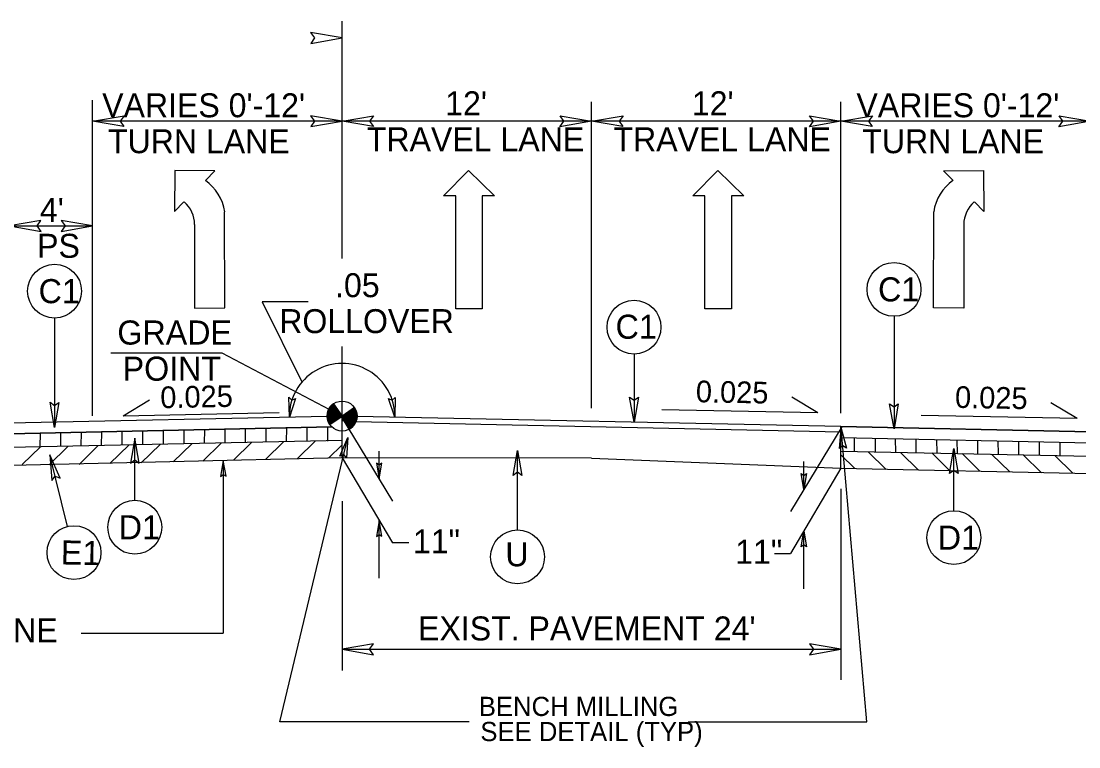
# Model space of a CAD drawing. Extents: x 2176024 to 2177225, y 75947 to 76635.
# Drawn here: x 2176290.4 to 2176341.3, y 76551.8 to 76586.8 of the extents above; entities that cross this region are included whole.
import ezdxf

# ---------------------------------------------------------------- set-up
doc = ezdxf.new("R2010")
doc.units = 0
for name, color, linetype in [('Exist XS Ground Line', 7, 'Continuous'), ('Old_Level_1', 7, 'Continuous'), ('Old_Level_11', 7, 'Continuous'), ('Old_Level_4', 7, 'Continuous'), ('Prop Dimension', 7, 'Continuous'), ('Prop Lane Arrow CELL', 7, 'Continuous'), ('Typical Curb CELL', 7, 'Continuous'), ('Typical Grade Point Symbol CELL', 7, 'Continuous'), ('Typical Pavement Slope CELL', 7, 'Continuous'), ('Typical Pavement Slope Information CELL', 7, 'Continuous'), ('Typical Shoulder Slope CELL', 7, 'Continuous'), ('Typical Slope Point Local CELL', 7, 'Continuous'), ('Typical Terminator CELL', 7, 'Continuous'), ('Typical Text General CELL', 7, 'Continuous')]:
    doc.layers.add(name, color=color, linetype=linetype)

msp = doc.modelspace()

# ---------------------------------------------------------------- linework, layer by layer
at = {"layer": 'Exist XS Ground Line'}
for q in [(2176305.841, 76565.736), (2176329.841, 76565.236)]:
    msp.add_line((2176317.841, 76565.72), q, dxfattribs=at)
at = {"layer": 'Old_Level_1'}
for p, q in [((2176291.326, 76566.266), (2176291.331, 76566.935)), ((2176292.315, 76566.283), (2176292.32, 76566.956)), ((2176293.298, 76566.302), (2176293.303, 76566.976)), ((2176294.275, 76566.325), (2176294.281, 76566.997)), ((2176295.264, 76566.347), (2176295.27, 76567.017)), ((2176296.253, 76566.366), (2176296.259, 76567.038)), ((2176297.25, 76566.389), (2176297.256, 76567.059)), ((2176298.24, 76566.412), (2176298.245, 76567.079)), ((2176299.229, 76566.433), (2176299.234, 76567.1)), ((2176300.21, 76566.454), (2176300.215, 76567.12)), ((2176301.189, 76566.472), (2176301.195, 76567.141)), ((2176302.186, 76566.493), (2176302.192, 76567.161)), ((2176303.174, 76566.515), (2176303.179, 76567.182)), ((2176304.163, 76566.529), (2176304.169, 76567.203)), ((2176305.153, 76566.549), (2176305.158, 76567.223)), ((2176296.184, 76565.5), (2176297.084, 76566.383)), ((2176297.722, 76565.551), (2176298.607, 76566.422)), ((2176299.15, 76565.586), (2176300.023, 76566.444)), ((2176300.618, 76565.623), (2176301.485, 76566.476)), ((2176302.155, 76565.654), (2176303.024, 76566.509)), ((2176303.679, 76565.694), (2176304.54, 76566.541)), ((2176330.496, 76566.049), (2176330.491, 76566.698)), ((2176331.502, 76566.024), (2176331.497, 76566.677)), ((2176332.476, 76566.012), (2176332.471, 76566.657)), ((2176333.466, 76565.983), (2176333.46, 76566.637)), ((2176334.463, 76565.976), (2176334.457, 76566.616)), ((2176335.442, 76565.955), (2176335.437, 76566.595)), ((2176336.423, 76565.935), (2176336.418, 76566.575)), ((2176337.412, 76565.91), (2176337.407, 76566.554)), ((2176338.401, 76565.891), (2176338.396, 76566.534)), ((2176339.399, 76565.867), (2176339.393, 76566.513)), ((2176340.388, 76565.854), (2176340.382, 76566.492)), ((2176290.46, 76565.413), (2176291.331, 76566.269)), ((2176291.749, 76565.403), (2176292.654, 76566.293)), ((2176293.197, 76565.425), (2176294.115, 76566.328)), ((2176294.664, 76565.462), (2176295.576, 76566.358)), ((2176305.188, 76565.727), (2176305.841, 76566.369)), ((2176330.512, 76565.222), (2176329.843, 76565.88)), ((2176332.022, 76565.185), (2176331.155, 76566.037)), ((2176333.57, 76565.146), (2176332.702, 76566.001)), ((2176335.069, 76565.131), (2176334.205, 76565.981)), ((2176336.527, 76565.104), (2176335.669, 76565.947)), ((2176337.957, 76565.067), (2176337.091, 76565.919)), ((2176339.493, 76565.017), (2176338.61, 76565.884)), ((2176340.992, 76565.001), (2176340.125, 76565.853))]:
    msp.add_line(p, q, dxfattribs=at)
at = {"layer": 'Old_Level_11'}
for p, q in [((2176304.207, 76573.248), (2176301.999, 76573.248)), ((2176301.999, 76573.248), (2176303.911, 76569.392)), ((2176332.395, 76572.555), (2176332.395, 76567.14)), ((2176292.006, 76572.47), (2176292.006, 76567.208)), ((2176294.722, 76570.79), (2176300.053, 76570.79)), ((2176300.053, 76570.79), (2176305.841, 76567.75)), ((2176319.887, 76570.735), (2176319.887, 76567.457)), ((2176295.871, 76563.695), (2176295.871, 76566.691)), ((2176292.635, 76562.435), (2176291.789, 76565.878)), ((2176314.282, 76562.267), (2176314.282, 76566.097)), ((2176335.273, 76563.195), (2176335.273, 76566.191))]:
    msp.add_line(p, q, dxfattribs=at)
for points in [[(2176292.213, 76568.408), (2176292.006, 76567.208), (2176291.793, 76568.414), (2176292.006, 76568.261)], [(2176320.094, 76568.657), (2176319.887, 76567.457), (2176319.674, 76568.664), (2176319.887, 76568.511)], [(2176332.601, 76568.34), (2176332.395, 76567.14), (2176332.181, 76568.347), (2176332.395, 76568.194)], [(2176329.774, 76566.188), (2176329.859, 76567.159), (2176330.109, 76566.211), (2176329.929, 76566.319)], [(2176296.078, 76565.491), (2176295.871, 76566.691), (2176295.658, 76565.485), (2176295.871, 76565.638)], [(2176305.736, 76565.825), (2176306.123, 76566.719), (2176306.062, 76565.741), (2176305.925, 76565.9)], [(2176292.279, 76564.763), (2176291.789, 76565.878), (2176291.874, 76564.656), (2176292.043, 76564.856)], [(2176314.076, 76564.897), (2176314.282, 76566.097), (2176314.496, 76564.89), (2176314.282, 76565.044)], [(2176335.066, 76564.991), (2176335.273, 76566.191), (2176335.486, 76564.985), (2176335.273, 76565.138)]]:
    msp.add_lwpolyline(points, close=True, dxfattribs=at)
for centre in [(2176292.012, 76573.766), (2176332.395, 76573.851), (2176319.887, 76572.031), (2176295.871, 76562.399), (2176335.273, 76561.899), (2176292.945, 76561.177), (2176314.282, 76560.971)]:
    msp.add_circle(centre, 1.296, dxfattribs=at)
msp.add_arc((2176305.841, 76567.75), 2.534, 358.8065, 181.1935, dxfattribs=at)
at = {"layer": 'Old_Level_4'}
for p, q in [((2176310.727, 76578.354), (2176311.929, 76579.576)), ((2176311.929, 76579.576), (2176313.171, 76578.354)), ((2176322.717, 76578.354), (2176323.92, 76579.576)), ((2176323.92, 76579.576), (2176325.162, 76578.354)), ((2176311.309, 76578.354), (2176310.727, 76578.354)), ((2176311.309, 76572.922), (2176311.309, 76578.354)), ((2176313.171, 76578.354), (2176312.589, 76578.354)), ((2176312.589, 76578.354), (2176312.589, 76572.922)), ((2176323.299, 76578.354), (2176322.717, 76578.354)), ((2176323.299, 76572.922), (2176323.299, 76578.354)), ((2176325.162, 76578.354), (2176324.58, 76578.354)), ((2176324.58, 76578.354), (2176324.58, 76572.922)), ((2176312.589, 76572.922), (2176311.309, 76572.922)), ((2176324.58, 76572.922), (2176323.299, 76572.922))]:
    msp.add_line(p, q, dxfattribs=at)
at = {"layer": 'Prop Dimension'}
for p, q in [((2176305.841, 76575.332), (2176305.841, 76586.766)), ((2176293.841, 76567.766), (2176293.841, 76582.965)), ((2176317.841, 76568.127), (2176317.841, 76582.883)), ((2176329.841, 76567.899), (2176329.841, 76582.883)), ((2176305.841, 76581.946), (2176293.841, 76581.946)), ((2176317.841, 76581.946), (2176305.841, 76581.946)), ((2176329.841, 76581.946), (2176317.841, 76581.946)), ((2176341.841, 76581.946), (2176329.841, 76581.946)), ((2176289.841, 76576.903), (2176293.841, 76576.903)), ((2176305.841, 76567.75), (2176305.841, 76571.093)), ((2176305.796, 76567.737), (2176308.266, 76563.655)), ((2176329.886, 76567.237), (2176327.416, 76563.155)), ((2176331.081, 76553.036), (2176329.859, 76567.159)), ((2176302.847, 76553.036), (2176306.123, 76566.719)), ((2176307.629, 76564.73), (2176307.629, 76566.058)), ((2176300.129, 76565.605), (2176300.129, 76557.301)), ((2176305.841, 76565.736), (2176308.266, 76561.641)), ((2176328.052, 76564.23), (2176328.052, 76565.558)), ((2176329.841, 76565.236), (2176327.416, 76561.141)), ((2176329.841, 76564.24), (2176329.841, 76555.057)), ((2176305.841, 76563.661), (2176305.841, 76555.497)), ((2176307.629, 76559.94), (2176307.629, 76562.716)), ((2176328.052, 76559.44), (2176328.052, 76562.216)), ((2176309.046, 76561.641), (2176308.266, 76561.641)), ((2176326.636, 76561.141), (2176327.416, 76561.141)), ((2176293.298, 76557.301), (2176300.129, 76557.301)), ((2176305.841, 76556.522), (2176329.841, 76556.522)), ((2176311.958, 76553.036), (2176302.847, 76553.036)), ((2176322.488, 76553.036), (2176331.081, 76553.036))]:
    msp.add_line(p, q, dxfattribs=at)
at = {"layer": 'Prop Lane Arrow CELL'}
for p, q in [((2176297.794, 76579.576), (2176297.775, 76577.601)), ((2176299.725, 76579.558), (2176297.794, 76579.576)), ((2176299.265, 76579.096), (2176299.725, 76579.558)), ((2176334.773, 76579.558), (2176336.703, 76579.576)), ((2176335.233, 76579.096), (2176334.773, 76579.558)), ((2176336.703, 76579.576), (2176336.722, 76577.601)), ((2176297.775, 76577.601), (2176298.235, 76578.063)), ((2176300.198, 76572.955), (2176300.189, 76577.584)), ((2176334.3, 76572.955), (2176334.308, 76577.584)), ((2176336.722, 76577.601), (2176336.262, 76578.063)), ((2176298.742, 76576.967), (2176298.749, 76572.952)), ((2176335.755, 76576.967), (2176335.748, 76572.952)), ((2176298.749, 76572.952), (2176300.198, 76572.955)), ((2176335.748, 76572.952), (2176334.3, 76572.955))]:
    msp.add_line(p, q, dxfattribs=at)
for centre, radius, start, end in [((2176297.919, 76577.232), 2.305, 8.7824, 54.0941), ((2176336.579, 76577.232), 2.305, 125.9059, 171.2176), ((2176297.312, 76576.969), 1.437, 0.1063, 49.7645), ((2176337.185, 76576.969), 1.437, 130.2355, 179.8937)]:
    msp.add_arc(centre, radius, start, end, dxfattribs=at)
at = {"layer": 'Typical Curb CELL'}
for p, q in [((2176305.841, 76565.736), (2176305.841, 76567.75)), ((2176329.841, 76565.236), (2176329.841, 76567.25))]:
    msp.add_line(p, q, dxfattribs=at)
at = {"layer": 'Typical Grade Point Symbol CELL'}
for p, q in [((2176305.429, 76568.342), (2176305.841, 76567.75)), ((2176305.841, 76567.75), (2176306.432, 76568.162)), ((2176305.248, 76567.34), (2176305.841, 76567.75)), ((2176305.841, 76567.75), (2176305.248, 76567.34)), ((2176306.253, 76567.158), (2176305.841, 76567.75))]:
    msp.add_line(p, q, dxfattribs=at)
for points in [[(2176305.596, 76568.102), (2176305.12, 76567.771)], [(2176305.604, 76568.091), (2176305.12, 76567.754)], [(2176305.612, 76568.079), (2176305.12, 76567.737)], [(2176305.587, 76568.114), (2176305.121, 76567.789)], [(2176305.62, 76568.067), (2176305.121, 76567.719)], [(2176305.629, 76568.055), (2176305.121, 76567.702)], [(2176305.579, 76568.126), (2176305.122, 76567.808)], [(2176305.637, 76568.043), (2176305.123, 76567.685)], [(2176305.571, 76568.138), (2176305.124, 76567.827)], [(2176305.645, 76568.031), (2176305.124, 76567.669)], [(2176305.563, 76568.15), (2176305.126, 76567.846)], [(2176305.653, 76568.02), (2176305.126, 76567.653)], [(2176305.554, 76568.162), (2176305.128, 76567.865)], [(2176305.661, 76568.008), (2176305.129, 76567.637)], [(2176305.546, 76568.173), (2176305.132, 76567.885)], [(2176305.67, 76567.996), (2176305.132, 76567.622)], [(2176305.678, 76567.984), (2176305.135, 76567.606)], [(2176305.538, 76568.185), (2176305.137, 76567.906)], [(2176305.686, 76567.972), (2176305.138, 76567.591)], [(2176305.694, 76567.96), (2176305.141, 76567.575)], [(2176305.53, 76568.197), (2176305.142, 76567.927)], [(2176305.703, 76567.949), (2176305.145, 76567.561)], [(2176305.521, 76568.209), (2176305.148, 76567.949)], [(2176305.711, 76567.937), (2176305.149, 76567.546)], [(2176305.513, 76568.221), (2176305.154, 76567.971)], [(2176305.719, 76567.925), (2176305.154, 76567.531)], [(2176305.727, 76567.913), (2176305.159, 76567.518)], [(2176305.505, 76568.233), (2176305.162, 76567.994)], [(2176305.497, 76568.244), (2176305.171, 76568.017)], [(2176305.489, 76568.256), (2176305.181, 76568.042)], [(2176305.48, 76568.268), (2176305.194, 76568.069)], [(2176305.472, 76568.28), (2176305.208, 76568.096)], [(2176305.464, 76568.292), (2176305.225, 76568.125)], [(2176305.456, 76568.304), (2176305.244, 76568.156)], [(2176305.447, 76568.315), (2176305.271, 76568.193)], [(2176305.439, 76568.327), (2176305.305, 76568.234)], [(2176305.431, 76568.339), (2176305.366, 76568.294)], [(2176306.436, 76568.156), (2176306.436, 76568.156), (2176305.844, 76567.745)], [(2176306.444, 76568.145), (2176305.853, 76567.733)], [(2176306.451, 76568.132), (2176305.861, 76567.721)], [(2176306.46, 76568.12), (2176305.869, 76567.709)], [(2176306.466, 76568.107), (2176305.877, 76567.697)], [(2176306.473, 76568.095), (2176305.886, 76567.686)], [(2176306.48, 76568.082), (2176305.894, 76567.674)], [(2176306.487, 76568.069), (2176305.902, 76567.662)], [(2176306.494, 76568.056), (2176305.91, 76567.65)], [(2176306.5, 76568.043), (2176305.919, 76567.638)], [(2176306.505, 76568.029), (2176305.927, 76567.626)], [(2176306.511, 76568.015), (2176305.935, 76567.615)], [(2176306.517, 76568.002), (2176305.943, 76567.603)], [(2176306.521, 76567.987), (2176305.952, 76567.591)], [(2176306.526, 76567.973), (2176305.96, 76567.579)], [(2176306.531, 76567.959), (2176305.968, 76567.567)], [(2176306.535, 76567.944), (2176305.976, 76567.555)], [(2176306.539, 76567.93), (2176305.984, 76567.544)], [(2176306.542, 76567.914), (2176305.993, 76567.532)], [(2176305.736, 76567.901), (2176305.164, 76567.503)], [(2176305.744, 76567.889), (2176305.169, 76567.49)], [(2176305.752, 76567.878), (2176305.175, 76567.476)], [(2176305.76, 76567.866), (2176305.18, 76567.462)], [(2176305.769, 76567.854), (2176305.186, 76567.449)], [(2176305.777, 76567.842), (2176305.193, 76567.436)], [(2176305.785, 76567.83), (2176305.199, 76567.422)], [(2176305.793, 76567.818), (2176305.206, 76567.409)], [(2176305.801, 76567.807), (2176305.212, 76567.397)], [(2176305.81, 76567.795), (2176305.219, 76567.384)], [(2176305.818, 76567.783), (2176305.228, 76567.372)], [(2176305.826, 76567.771), (2176305.235, 76567.359)], [(2176305.834, 76567.759), (2176305.243, 76567.347), (2176305.243, 76567.347)], [(2176306.545, 76567.899), (2176306.001, 76567.52)], [(2176306.548, 76567.883), (2176306.009, 76567.508)], [(2176306.551, 76567.868), (2176306.017, 76567.496)], [(2176306.554, 76567.852), (2176306.026, 76567.484)], [(2176306.556, 76567.836), (2176306.034, 76567.473)], [(2176306.558, 76567.819), (2176306.042, 76567.461)], [(2176306.559, 76567.803), (2176306.05, 76567.449)], [(2176306.561, 76567.787), (2176306.059, 76567.437)], [(2176306.561, 76567.769), (2176306.067, 76567.425)], [(2176306.562, 76567.752), (2176306.075, 76567.413)], [(2176306.561, 76567.734), (2176306.083, 76567.402)], [(2176306.561, 76567.716), (2176306.092, 76567.39)], [(2176306.56, 76567.698), (2176306.1, 76567.378)], [(2176306.558, 76567.679), (2176306.108, 76567.366)], [(2176306.555, 76567.66), (2176306.116, 76567.354)], [(2176306.553, 76567.641), (2176306.124, 76567.342)], [(2176306.55, 76567.621), (2176306.133, 76567.331)], [(2176306.546, 76567.601), (2176306.141, 76567.319)], [(2176306.541, 76567.58), (2176306.149, 76567.307)], [(2176306.535, 76567.558), (2176306.157, 76567.295)], [(2176306.529, 76567.536), (2176306.166, 76567.283)], [(2176306.521, 76567.513), (2176306.174, 76567.271)], [(2176306.512, 76567.489), (2176306.182, 76567.26)], [(2176306.502, 76567.465), (2176306.19, 76567.248)], [(2176306.491, 76567.439), (2176306.199, 76567.236)], [(2176306.478, 76567.413), (2176306.207, 76567.224)], [(2176306.461, 76567.383), (2176306.215, 76567.212)], [(2176306.442, 76567.352), (2176306.223, 76567.2)], [(2176306.417, 76567.318), (2176306.232, 76567.189)], [(2176306.384, 76567.277), (2176306.24, 76567.177)], [(2176306.332, 76567.223), (2176306.248, 76567.165)]]:
    msp.add_lwpolyline(points, dxfattribs=at)
msp.add_circle((2176305.841, 76567.751), 0.721, dxfattribs=at)
for start, end in [(124.8249, 214.8249), (304.8249, 34.8249)]:
    msp.add_arc((2176305.841, 76567.751), 0.721, start, end, dxfattribs=at)
at = {"layer": 'Typical Pavement Slope CELL'}
for p, q in [((2176305.841, 76567.75), (2176305.841, 76567.5)), ((2176306.511, 76567.486), (2176329.841, 76567)), ((2176305.345, 76567.227), (2176289.841, 76566.904)), ((2176329.841, 76566.712), (2176341.841, 76566.462)), ((2176329.841, 76566.068), (2176341.841, 76565.818)), ((2176305.841, 76565.736), (2176286.947, 76565.304))]:
    msp.add_line(p, q, dxfattribs=at)
at = {"layer": 'Typical Pavement Slope Information CELL'}
for p, q in [((2176295.311, 76567.77), (2176296.572, 76568.532)), ((2176328.733, 76567.903), (2176327.472, 76568.666)), ((2176295.311, 76567.77), (2176302.817, 76567.92)), ((2176328.733, 76567.903), (2176321.227, 76568.054)), ((2176341.2, 76567.632), (2176339.939, 76568.394)), ((2176341.2, 76567.632), (2176333.694, 76567.782))]:
    msp.add_line(p, q, dxfattribs=at)
at = {"layer": 'Typical Shoulder Slope CELL'}
for p, q in [((2176305.841, 76566.568), (2176289.841, 76566.235)), ((2176329.841, 76565.236), (2176341.841, 76564.986))]:
    msp.add_line(p, q, dxfattribs=at)
at = {"layer": 'Typical Slope Point Local CELL'}
for p, q in [((2176305.121, 76567.702), (2176305.121, 76567.702)), ((2176305.126, 76567.653), (2176305.126, 76567.653)), ((2176305.141, 76567.575), (2176305.141, 76567.576)), ((2176305.145, 76567.561), (2176305.145, 76567.561)), ((2176305.154, 76567.531), (2176305.154, 76567.531)), ((2176305.186, 76567.449), (2176305.186, 76567.449)), ((2176305.199, 76567.422), (2176305.199, 76567.422)), ((2176305.206, 76567.409), (2176305.206, 76567.409)), ((2176305.212, 76567.397), (2176305.213, 76567.397)), ((2176306.511, 76567.486), (2176329.841, 76567)), ((2176306.521, 76567.513), (2176306.521, 76567.513)), ((2176306.529, 76567.536), (2176306.529, 76567.536)), ((2176306.541, 76567.58), (2176306.541, 76567.579)), ((2176306.546, 76567.601), (2176306.545, 76567.6)), ((2176306.55, 76567.621), (2176306.55, 76567.621)), ((2176306.553, 76567.641), (2176306.553, 76567.641)), ((2176306.56, 76567.698), (2176306.559, 76567.698)), ((2176329.841, 76567.25), (2176306.561, 76567.735)), ((2176306.561, 76567.716), (2176306.561, 76567.716)), ((2176305.219, 76567.384), (2176305.22, 76567.384)), ((2176305.235, 76567.359), (2176305.235, 76567.36)), ((2176305.243, 76567.347), (2176305.243, 76567.348)), ((2176305.249, 76567.339), (2176305.248, 76567.34)), ((2176305.248, 76567.34), (2176305.248, 76567.34)), ((2176329.841, 76567.25), (2176341.841, 76567)), ((2176341.841, 76567), (2176329.841, 76567.25)), ((2176329.841, 76567.25), (2176329.841, 76566.712)), ((2176329.841, 76567), (2176329.841, 76567.25)), ((2176329.841, 76566.712), (2176341.841, 76566.462))]:
    msp.add_line(p, q, dxfattribs=at)
for points in [[(2176305.12, 76567.735), (2176289.841, 76567.417), (2176289.841, 76566.904), (2176305.345, 76567.227)], [(2176305.121, 76567.702), (2176305.121, 76567.702)], [(2176305.126, 76567.653), (2176305.126, 76567.653)], [(2176305.141, 76567.575), (2176305.141, 76567.575)], [(2176305.145, 76567.561), (2176305.145, 76567.561)], [(2176305.154, 76567.531), (2176305.154, 76567.531)], [(2176305.186, 76567.449), (2176305.186, 76567.449)], [(2176305.199, 76567.422), (2176305.199, 76567.422)], [(2176305.206, 76567.409), (2176305.206, 76567.409)], [(2176305.213, 76567.397), (2176305.212, 76567.397)], [(2176306.521, 76567.513), (2176306.521, 76567.513)], [(2176306.529, 76567.536), (2176306.529, 76567.536)], [(2176306.541, 76567.58), (2176306.541, 76567.58)], [(2176306.546, 76567.601), (2176306.546, 76567.601)], [(2176306.55, 76567.621), (2176306.55, 76567.621)], [(2176306.553, 76567.641), (2176306.553, 76567.641)], [(2176306.559, 76567.698), (2176306.56, 76567.698)], [(2176306.561, 76567.716), (2176306.561, 76567.716)], [(2176305.22, 76567.384), (2176305.219, 76567.384)], [(2176305.235, 76567.36), (2176305.235, 76567.359)], [(2176305.243, 76567.348), (2176305.243, 76567.347)]]:
    msp.add_lwpolyline(points, dxfattribs=at)
for start, end in [(181.2559, 183.8761), (183.8895, 185.2021), (185.2021, 186.5121), (186.5121, 187.8094), (187.8245, 189.0767), (189.0767, 191.5882), (191.5882, 192.8361), (192.8361, 194.0754), (194.0907, 195.2968), (195.2976, 197.7127), (197.7154, 200.0946), (200.0946, 204.7878), (204.7881, 207.109), (207.1121, 208.2646), (208.2653, 209.4175), (209.4186, 210.5682), (338.4481, 340.731), (340.7368, 342.6429), (342.646, 346.2404), (346.2648, 347.9455), (347.9775, 349.598), (349.5984, 351.2038), (351.2196, 352.7539), (352.7539, 354.2837), (354.2837, 355.7778), (355.8127, 357.2394), (358.6425, 358.745), (357.2652, 358.6425), (210.5718, 211.7158), (211.7158, 212.8649), (212.8666, 214.0118), (214.0122, 214.7719), (214.8249, 226.5883)]:
    msp.add_arc((2176305.841, 76567.751), 0.721, start, end, dxfattribs=at)
at = {"layer": 'Typical Terminator CELL'}
for points in [[(2176304.331, 76585.697), (2176305.841, 76585.957), (2176304.323, 76586.225), (2176304.516, 76585.957)], [(2176295.35, 76581.686), (2176293.841, 76581.946), (2176295.359, 76582.214), (2176295.166, 76581.946)], [(2176304.331, 76581.686), (2176305.841, 76581.946), (2176304.323, 76582.214), (2176304.516, 76581.946)], [(2176307.35, 76581.686), (2176305.841, 76581.946), (2176307.359, 76582.214), (2176307.166, 76581.946)], [(2176316.331, 76582.206), (2176317.841, 76581.946), (2176316.323, 76581.677), (2176316.516, 76581.946)], [(2176319.35, 76581.686), (2176317.841, 76581.946), (2176319.359, 76582.214), (2176319.166, 76581.946)], [(2176328.331, 76582.206), (2176329.841, 76581.946), (2176328.323, 76581.677), (2176328.516, 76581.946)], [(2176331.35, 76581.686), (2176329.841, 76581.946), (2176331.359, 76582.214), (2176331.166, 76581.946)], [(2176340.331, 76582.206), (2176341.841, 76581.946), (2176340.323, 76581.677), (2176340.516, 76581.946)], [(2176291.35, 76577.163), (2176289.841, 76576.903), (2176291.359, 76576.634), (2176291.166, 76576.903)], [(2176292.331, 76576.643), (2176293.841, 76576.903), (2176292.323, 76577.171), (2176292.516, 76576.903)], [(2176303.609, 76568.599), (2176303.307, 76567.697), (2176303.286, 76568.654), (2176303.432, 76568.51)], [(2176308.397, 76568.648), (2176308.374, 76567.697), (2176308.072, 76568.605), (2176308.254, 76568.511)], [(2176300.259, 76564.85), (2176300.129, 76565.605), (2176299.995, 76564.846), (2176300.129, 76564.943)], [(2176307.497, 76565.484), (2176307.629, 76564.73), (2176307.761, 76565.489), (2176307.627, 76565.392)], [(2176328.185, 76564.984), (2176328.052, 76564.23), (2176327.921, 76564.989), (2176328.054, 76564.892)], [(2176307.761, 76561.962), (2176307.629, 76562.716), (2176307.497, 76561.957), (2176307.631, 76562.054)], [(2176327.92, 76561.462), (2176328.052, 76562.216), (2176328.184, 76561.457), (2176328.05, 76561.554)], [(2176307.35, 76556.782), (2176305.841, 76556.522), (2176307.359, 76556.254), (2176307.166, 76556.522)], [(2176328.331, 76556.262), (2176329.841, 76556.522), (2176328.323, 76556.791), (2176328.516, 76556.522)]]:
    msp.add_lwpolyline(points, close=True, dxfattribs=at)

# ---------------------------------------------------------------- texts
at = {"layer": 'Old_Level_11'}
for s, rotation, p in [('C1', 0.0003, (2176291.243, 76573.186)), ('C1', 0.0003, (2176331.626, 76573.271)), ('C1', 0.0003, (2176318.998, 76571.473)), ('GRADE', 359.9998, (2176295.031, 76571.194)), ('POINT', 359.9998, (2176295.284, 76569.454)), ('D1', 0.0003, (2176295.099, 76561.819)), ('D1', 0.0003, (2176334.5, 76561.319)), ('E1', 358.8249, (2176292.304, 76560.61)), ('U', 0.0003, (2176313.696, 76560.517))]:
    msp.add_text(s, height=1.16, rotation=rotation, dxfattribs=at).set_placement(p)
for p in [(2176309.25, 76561.14), (2176324.754, 76560.64)]:
    msp.add_text('11"', height=1.1533, dxfattribs=at).set_placement(p)
at = {"layer": 'Typical Pavement Slope Information CELL'}
for rotation, p in [(358.8543, (2176322.853, 76568.421)), (1.1457, (2176297.107, 76568.128)), (358.8543, (2176335.32, 76568.15))]:
    msp.add_text('0.025', height=1.0429, rotation=rotation, dxfattribs=at).set_placement(p)
at = {"layer": 'Typical Text General CELL'}
for s, height, p in [("VARIES 0'-12'", 1.15334, (2176294.301, 76582.138)), ("12' ", 1.1533, (2176310.803, 76582.234)), ("12' ", 1.1533, (2176322.668, 76582.234)), ("VARIES 0'-12'", 1.15334, (2176330.586, 76582.138)), ('TRAVEL LANE', 1.15334, (2176307.033, 76580.504)), ('TRAVEL LANE', 1.15334, (2176318.899, 76580.504)), (' TURN LANE', 1.1533, (2176294.154, 76580.408)), (' TURN LANE', 1.1533, (2176330.439, 76580.408)), ("4'", 1.1533, (2176291.304, 76577.103)), ('PS', 1.1533, (2176291.174, 76575.373)), ('GRADE TO THIS LINE', 1.15334, (2176276.309, 76556.855)), ("EXIST. PAVEMENT 24'", 1.15334, (2176309.498, 76556.95)), ('BENCH MILLING', 0.92267, (2176312.42, 76553.312)), ('SEE DETAIL (TYP)', 0.92267, (2176312.495, 76552.102))]:
    msp.add_text(s, height=height, dxfattribs=at).set_placement(p)
for s, p in [('.05', (2176305.505, 76573.475)), ('ROLLOVER', (2176302.82, 76571.745))]:
    msp.add_text(s, height=1.1533, rotation=360, dxfattribs=at).set_placement(p)

doc.saveas('drawing.dxf')
